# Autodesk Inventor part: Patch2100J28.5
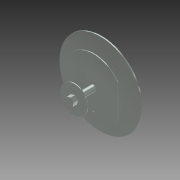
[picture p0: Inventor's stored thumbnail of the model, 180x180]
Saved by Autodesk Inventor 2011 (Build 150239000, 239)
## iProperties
Created: 2014-07
Part Number: Patch2100J28.5
Document SubType Name: Modeling
Designer: Evgeny
Density: 1 g/cm^3
Author: Evgeny
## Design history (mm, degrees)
sketch "Эскиз1"
  geometry: L1 (32.81, 23.315)-(32.81, -23.315); L2 (-32.81, -23.315)-(-32.81, 23.315); C1 r 1.35 at (0, -28.5); A1 r 40.25 centre (0, 0) between (32.81, 23.315) and (-32.81, 23.315); A2 r 40.25 centre (0, 0) between (-32.81, -23.315) and (32.81, -23.315); 1 further point
  constraints: 4 end point, 4 point on circle, 3 centre point, 1 coincident, 1 parallel
  dimensions: "d5" = 2.7 diameter of C1; "d6" = 28.5 distance of point (0, 0) C1.centre; "d38" = 65.62 distance between parallel lines of L1 L2; "d39" = 32.81 distance from line of L2 point (0, 0)
extrude "Выдавливание1" new body sketch "Эскиз1" distance "d7" = 1; taper "d8" = 0 deg
sketch "Эскиз2"
  geometry: C1 r 4 at (0, 0)
  constraints: 1 centre point
  dimensions: "d9" = 8 diameter of C1
extrude "Выдавливание2" join sketch "Эскиз2" distance "d10" = 8.66; taper "d11" = 0 deg
sketch "Эскиз3"
  geometry: C1 r 4 at (0, 0) reference; C2 r 56 at (0, 0); C3 r 4 at (0, -28.5)
  constraints: 2 centre point, 1 coincident
  dimensions: "d12" = 112 diameter of C2; "d13" = 8 diameter of C3; "d14" = 28.5 distance of C3.centre C1.centre
extrude "Выдавливание3" join sketch "Эскиз3" distance "d15" = 1.5; taper "d16" = 0 deg
sketch "Эскиз4"
  geometry: C1 r 4 at (0, 0)
  constraints: 1 centre point
  dimensions: "d17" = 8 diameter of C1
extrude "Выдавливание4" join sketch "Эскиз4" distance "d18" = 25.5; taper "d19" = 0 deg
sketch "Эскиз5"
  geometry: C1 r 4 at (0, 0) reference; C2 r 18.5 at (0, 0)
  constraints: 1 centre point, 1 coincident
  dimensions: "d20" = 37 diameter of C2
extrude "Выдавливание5" join sketch "Эскиз5" distance "d21" = 1; taper "d22" = 0 deg
sketch "Эскиз6"
  geometry: L1 (-1.421, -5.596)-(-5.557, -1.567); L2 (-5.557, -1.567)-(-4.136, 4.029); L3 (-4.136, 4.029)-(1.421, 5.596); L4 (1.421, 5.596)-(5.557, 1.567); L5 (5.557, 1.567)-(4.136, -4.029); L6 (4.136, -4.029)-(-1.421, -5.596); C1 r 18.5 at (0, 0) reference; 1 further point
  constraints: 12 end point, 1 coincident, 13 other
  dimensions: "d24" = 10 distance between parallel lines of L6 L3
extrude "Выдавливание6" join sketch "Эскиз6" distance "d25" = 6; taper "d26" = 0 deg
sketch "Эскиз7"
  geometry: L1 (0, -5.774)-(-5, -2.887); L2 (-5, -2.887)-(-5, 2.887); L3 (-5, 2.887)-(0, 5.774); L4 (0, 5.774)-(5, 2.887); L5 (5, 2.887)-(5, -2.887); L6 (5, -2.887)-(0, -5.774); C1 r 56 at (0, 0) reference; 1 further point
  constraints: 12 end point, 1 coincident, 13 other
  dimensions: "d27" = 10 distance between parallel lines of L5 L2
extrude "Выдавливание7" join sketch "Эскиз7" distance "d28" = 6; taper "d29" = 0 deg
sketch "Эскиз8"
  geometry: C1 r 3 at (0, 0); 1 further point
  constraints: 1 centre point, 1 coincident
  dimensions: "d30" = 6 diameter of C1
extrude "Выдавливание8" join sketch "Эскиз8" distance "d31" = 6; taper "d32" = 0 deg
extrude "Выдавливание9" join sketch "Эскиз1" distance "d33" = 1.5; taper "d35" = 0 deg; dims "d34" = 10.16, "d36" = 0
node "Твердое тело1"
other parameters: "d0" = 75, "d37" = 80.5
